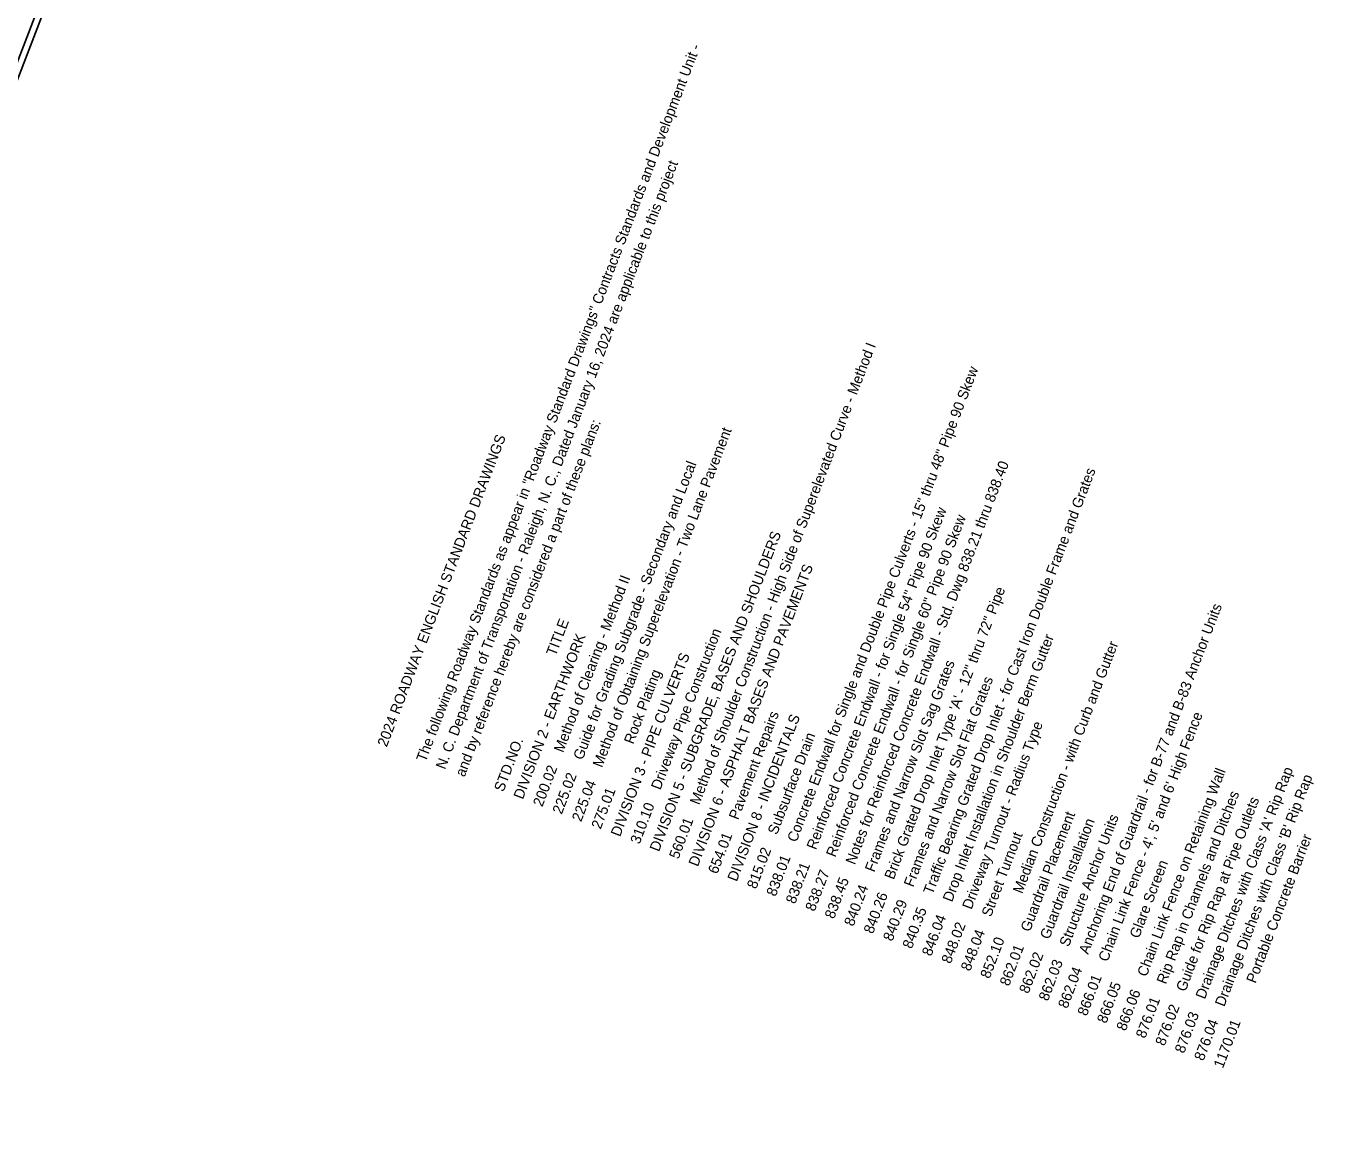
# Model space of a CAD drawing. Extents: x 1015221 to 1064345, y 619216 to 647967.
# Drawn here: x 1033081 to 1037125, y 636795 to 640203 of the extents above; entities that cross this region are included whole.
import ezdxf

# ---------------------------------------------------------------- set-up
doc = ezdxf.new("R2010")
doc.units = 0
for name, color, linetype in [('Sheet Plan CELL', 7, 'Continuous'), ('Sheet Plan Layout CELL', 7, 'Continuous'), ('Sheet Plot Border Inside CELL', 7, 'Continuous')]:
    doc.layers.add(name, color=color, linetype=linetype)

msp = doc.modelspace()

# ---------------------------------------------------------------- linework, layer by layer
at = {"layer": 'Sheet Plan CELL'}
msp.add_lwpolyline([(1033986, 642465.8), (1029682.3, 631264.1), (1037523.5, 628251.5), (1041827.2, 639453.2)], close=True, dxfattribs=at)
at = {"layer": 'Sheet Plot Border Inside CELL'}
msp.add_lwpolyline([(1037101.7, 627098), (1041881.8, 639539.4), (1034003.2, 642566.3), (1029223.2, 630125)], close=True, dxfattribs=at)

# ---------------------------------------------------------------- texts
at = {"layer": 'Sheet Plan Layout CELL'}
for s, height, p in [('The following Roadway Standards as appear in "Roadway Standard Drawings" Contracts Standards and Development Unit -', 31.9998, (1034307.4, 637941.1)), ('N. C. Department of Transportation - Raleigh, N. C., Dated January 16, 2024 are applicable to this project', 31.9998, (1034367.2, 637918.1)), ('560.01    Method of Shoulder Construction - High Side of Superelevated Curve - Method I', 32, (1035084.1, 637642.7)), ('838.01    Concrete Endwall for Single and Double Pipe Culverts - 15" thru 48" Pipe 90 Skew', 32, (1035382.8, 637527.9)), ('and by reference hereby are considered a part of these plans:', 32, (1034426.9, 637895.1)), ('2024 ROADWAY ENGLISH STANDARD DRAWINGS', 32, (1034187.9, 637987)), ('225.04    Method of Obtaining Superelevation - Two Lane Pavement', 32, (1034785.3, 637757.4)), ('225.02    Guide for Grading Subgrade - Secondary and Local', 32, (1034725.6, 637780.4)), ('838.45    Notes for Reinforced Concrete Endwall - Std. Dwg 838.21 thru 838.40', 32, (1035562, 637459)), ('840.35    Traffic Bearing Grated Drop Inlet - for Cast Iron Double Frame and Grates', 32, (1035801, 637367.2)), ('838.21    Reinforced Concrete Endwall - for Single 54" Pipe 90 Skew', 32, (1035442.5, 637504.9)), ('838.27    Reinforced Concrete Endwall - for Single 60" Pipe 90 Skew', 32, (1035502.3, 637482)), ('DIVISION 5 - SUBGRADE, BASES AND SHOULDERS', 32, (1035024.3, 637665.6)), ('DIVISION 6 - ASPHALT BASES AND PAVEMENTS', 32, (1035143.8, 637619.7)), ('200.02    Method of Clearing - Method II', 32, (1034665.9, 637803.3)), ('840.26    Brick Grated Drop Inlet Type \'A\' - 12" thru 72" Pipe', 32, (1035681.5, 637413.1)), ('862.04    Anchoring End of Guardrail - for B-77 and B-83 Anchor Units', 32, (1036278.9, 637183.6)), ('STD.NO.                       TITLE', 32, (1034546.4, 637849.2)), ('DIVISION 2 - EARTHWORK', 32, (1034606.1, 637826.3)), ('310.10    Driveway Pipe Construction', 32, (1034964.6, 637688.6)), ('846.04    Drop Inlet Installation in Shoulder Berm Gutter', 32, (1035860.7, 637344.3)), ('  Median Construction - with Curb and Gutter', 32, (1036131.7, 637514.4)), ('DIVISION 3 - PIPE CULVERTS', 32, (1034904.8, 637711.5)), ('840.24    Frames and Narrow Slot Sag Grates', 32, (1035621.7, 637436.1)), ('  Rock Plating', 32, (1034936.9, 637973.4)), ('840.29    Frames and Narrow Slot Flat Grates', 32, (1035741.2, 637390.2)), ('654.01    Pavement Repairs', 32, (1035203.5, 637596.8)), ('DIVISION 8 - INCIDENTALS', 32, (1035263.3, 637573.8)), ("866.01    Chain Link Fence - 4', 5' and 6' High Fence", 32, (1036338.6, 637160.6)), ('848.02    Driveway Turnout - Radius Type', 32, (1035920.5, 637321.3)), ('815.02    Subsurface Drain', 32, (1035323, 637550.9)), ('866.06    Chain Link Fence on Retaining Wall', 32, (1036458.1, 637114.7)), ("876.03    Drainage Ditches with Class 'A' Rip Rap", 32, (1036637.4, 637045.9)), ("876.04    Drainage Ditches with Class 'B' Rip Rap", 32, (1036697.1, 637022.9)), ('275.01', 32, (1034845.1, 637734.5)), ('876.01    Rip Rap in Channels and Ditches', 32, (1036517.9, 637091.8)), ('876.02    Guide for Rip Rap at Pipe Outlets', 32, (1036577.6, 637068.8)), ('862.01    Guardrail Placement', 32, (1036099.7, 637252.5)), ('862.02    Guardrail Installation', 32, (1036159.4, 637229.5)), ('862.03    Structure Anchor Units', 32, (1036219.2, 637206.6)), ('848.04    Street Turnout', 32, (1035980.2, 637298.4)), ('  Portable Concrete Barrier', 32, (1036848.7, 637238.9)), ('  Glare Screen', 32, (1036490.2, 637376.7)), ('852.10', 32, (1036039.9, 637275.4)), ('866.05', 32, (1036398.4, 637137.7)), ('1170.01', 32, (1036756.8, 637000))]:
    msp.add_text(s, height=height, rotation=68.983, dxfattribs=at).set_placement(p)

doc.saveas('drawing.dxf')
